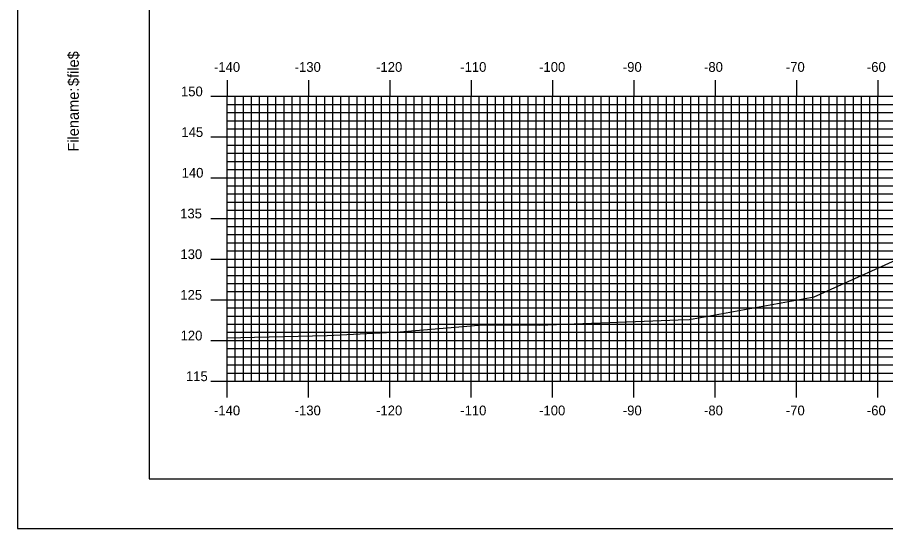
# Model space of a CAD drawing. Extents: x 851753 to 852097, y 364661 to 364881.
# Drawn here: x 851753.5 to 851860.2, y 364661.3 to 364724.1 of the extents above; entities that cross this region are included whole.
import ezdxf

# ---------------------------------------------------------------- set-up
doc = ezdxf.new("R2010")
doc.units = 0
for name, color, linetype in [('BORDER', 7, 'Continuous'), ('H_V ANNOTATION', 7, 'Continuous'), ('MAJOR', 7, 'Continuous'), ('MINOR', 7, 'Continuous'), ('PLOT BOUNDARY', 7, 'Continuous'), ('S_Roadway_Centerline', 7, 'Continuous')]:
    doc.layers.add(name, color=color, linetype=linetype)

msp = doc.modelspace()

# ---------------------------------------------------------------- linework, layer by layer
at = {"layer": 'BORDER'}
msp.add_lwpolyline([(851769.64, 364667.37), (852089.64, 364667.37), (852089.64, 364877.37), (851769.64, 364877.37)], close=True, dxfattribs=at)
at = {"layer": 'MAJOR'}
for p, q in [((851779.24, 364716.37), (851779.24, 364714.37)), ((851789.24, 364716.37), (851789.24, 364714.37)), ((851799.24, 364716.37), (851799.24, 364714.37)), ((851809.24, 364716.37), (851809.24, 364714.37)), ((851819.24, 364716.37), (851819.24, 364714.37)), ((851829.24, 364716.37), (851829.24, 364714.37)), ((851839.24, 364716.37), (851839.24, 364714.37)), ((851849.24, 364716.37), (851849.24, 364714.37)), ((851859.24, 364716.37), (851859.24, 364714.37)), ((851777.24, 364714.37), (851779.24, 364714.37)), ((851779.24, 364714.37), (852059.24, 364714.37)), ((851779.24, 364679.37), (851779.24, 364714.37)), ((851779.24, 364679.37), (851779.24, 364714.37)), ((851779.24, 364714.37), (852059.24, 364714.37)), ((851789.24, 364679.37), (851789.24, 364714.37)), ((851799.24, 364679.37), (851799.24, 364714.37)), ((851809.24, 364679.37), (851809.24, 364714.37)), ((851819.24, 364679.37), (851819.24, 364714.37)), ((851829.24, 364679.37), (851829.24, 364714.37)), ((851839.24, 364679.37), (851839.24, 364714.37)), ((851849.24, 364679.37), (851849.24, 364714.37)), ((851859.24, 364679.37), (851859.24, 364714.37)), ((851777.24, 364709.37), (851779.24, 364709.37)), ((851779.24, 364709.37), (852059.24, 364709.37)), ((851777.24, 364704.37), (851779.24, 364704.37)), ((851779.24, 364704.37), (852059.24, 364704.37)), ((851777.24, 364699.37), (851779.24, 364699.37)), ((851779.24, 364699.37), (852059.24, 364699.37)), ((851777.24, 364694.37), (851779.24, 364694.37)), ((851779.24, 364694.37), (852059.24, 364694.37)), ((851777.24, 364689.37), (851779.24, 364689.37)), ((851779.24, 364689.37), (852059.24, 364689.37)), ((851777.24, 364684.37), (851779.24, 364684.37)), ((851779.24, 364684.37), (852059.24, 364684.37)), ((851777.24, 364679.37), (851779.24, 364679.37)), ((851779.24, 364679.37), (852059.24, 364679.37)), ((851779.24, 364679.37), (852059.24, 364679.37)), ((851779.24, 364677.37), (851779.24, 364679.37)), ((851789.24, 364677.37), (851789.24, 364679.37)), ((851799.24, 364677.37), (851799.24, 364679.37)), ((851809.24, 364677.37), (851809.24, 364679.37)), ((851819.24, 364677.37), (851819.24, 364679.37)), ((851829.24, 364677.37), (851829.24, 364679.37)), ((851839.24, 364677.37), (851839.24, 364679.37)), ((851849.24, 364677.37), (851849.24, 364679.37)), ((851859.24, 364677.37), (851859.24, 364679.37))]:
    msp.add_line(p, q, dxfattribs=at)
at = {"layer": 'MINOR'}
for p, q in [((851780.24, 364679.37), (851780.24, 364714.37)), ((851781.24, 364679.37), (851781.24, 364714.37)), ((851782.24, 364679.37), (851782.24, 364714.37)), ((851783.24, 364679.37), (851783.24, 364714.37)), ((851784.24, 364679.37), (851784.24, 364714.37)), ((851785.24, 364679.37), (851785.24, 364714.37)), ((851786.24, 364679.37), (851786.24, 364714.37)), ((851787.24, 364679.37), (851787.24, 364714.37)), ((851788.24, 364679.37), (851788.24, 364714.37)), ((851790.24, 364679.37), (851790.24, 364714.37)), ((851791.24, 364679.37), (851791.24, 364714.37)), ((851792.24, 364679.37), (851792.24, 364714.37)), ((851793.24, 364679.37), (851793.24, 364714.37)), ((851794.24, 364679.37), (851794.24, 364714.37)), ((851795.24, 364679.37), (851795.24, 364714.37)), ((851796.24, 364679.37), (851796.24, 364714.37)), ((851797.24, 364679.37), (851797.24, 364714.37)), ((851798.24, 364679.37), (851798.24, 364714.37)), ((851800.24, 364679.37), (851800.24, 364714.37)), ((851801.24, 364679.37), (851801.24, 364714.37)), ((851802.24, 364679.37), (851802.24, 364714.37)), ((851803.24, 364679.37), (851803.24, 364714.37)), ((851804.24, 364679.37), (851804.24, 364714.37)), ((851805.24, 364679.37), (851805.24, 364714.37)), ((851806.24, 364679.37), (851806.24, 364714.37)), ((851807.24, 364679.37), (851807.24, 364714.37)), ((851808.24, 364679.37), (851808.24, 364714.37)), ((851810.24, 364679.37), (851810.24, 364714.37)), ((851811.24, 364679.37), (851811.24, 364714.37)), ((851812.24, 364679.37), (851812.24, 364714.37)), ((851813.24, 364679.37), (851813.24, 364714.37)), ((851814.24, 364679.37), (851814.24, 364714.37)), ((851815.24, 364679.37), (851815.24, 364714.37)), ((851816.24, 364679.37), (851816.24, 364714.37)), ((851817.24, 364679.37), (851817.24, 364714.37)), ((851818.24, 364679.37), (851818.24, 364714.37)), ((851820.24, 364679.37), (851820.24, 364714.37)), ((851821.24, 364679.37), (851821.24, 364714.37)), ((851822.24, 364679.37), (851822.24, 364714.37)), ((851823.24, 364679.37), (851823.24, 364714.37)), ((851824.24, 364679.37), (851824.24, 364714.37)), ((851825.24, 364679.37), (851825.24, 364714.37)), ((851826.24, 364679.37), (851826.24, 364714.37)), ((851827.24, 364679.37), (851827.24, 364714.37)), ((851828.24, 364679.37), (851828.24, 364714.37)), ((851830.24, 364679.37), (851830.24, 364714.37)), ((851831.24, 364679.37), (851831.24, 364714.37)), ((851832.24, 364679.37), (851832.24, 364714.37)), ((851833.24, 364679.37), (851833.24, 364714.37)), ((851834.24, 364679.37), (851834.24, 364714.37)), ((851835.24, 364679.37), (851835.24, 364714.37)), ((851836.24, 364679.37), (851836.24, 364714.37)), ((851837.24, 364679.37), (851837.24, 364714.37)), ((851838.24, 364679.37), (851838.24, 364714.37)), ((851840.24, 364679.37), (851840.24, 364714.37)), ((851841.24, 364679.37), (851841.24, 364714.37)), ((851842.24, 364679.37), (851842.24, 364714.37)), ((851843.24, 364679.37), (851843.24, 364714.37)), ((851844.24, 364679.37), (851844.24, 364714.37)), ((851845.24, 364679.37), (851845.24, 364714.37)), ((851846.24, 364679.37), (851846.24, 364714.37)), ((851847.24, 364679.37), (851847.24, 364714.37)), ((851848.24, 364679.37), (851848.24, 364714.37)), ((851850.24, 364679.37), (851850.24, 364714.37)), ((851851.24, 364679.37), (851851.24, 364714.37)), ((851852.24, 364679.37), (851852.24, 364714.37)), ((851853.24, 364679.37), (851853.24, 364714.37)), ((851854.24, 364679.37), (851854.24, 364714.37)), ((851855.24, 364679.37), (851855.24, 364714.37)), ((851856.24, 364679.37), (851856.24, 364714.37)), ((851857.24, 364679.37), (851857.24, 364714.37)), ((851858.24, 364679.37), (851858.24, 364714.37)), ((851779.24, 364713.37), (852059.24, 364713.37)), ((851779.24, 364713.37), (851781.25, 364713.37)), ((851779.24, 364712.37), (852059.24, 364712.37)), ((851779.24, 364712.37), (851781.25, 364712.37)), ((851779.24, 364711.37), (852059.24, 364711.37)), ((851779.24, 364711.37), (851781.25, 364711.37)), ((851779.24, 364710.37), (852059.24, 364710.37)), ((851779.24, 364710.37), (851781.25, 364710.37)), ((851779.24, 364708.37), (852059.24, 364708.37)), ((851779.24, 364708.37), (851781.25, 364708.37)), ((851779.24, 364707.37), (852059.24, 364707.37)), ((851779.24, 364707.37), (851781.25, 364707.37)), ((851779.24, 364706.37), (852059.24, 364706.37)), ((851779.24, 364706.37), (851781.25, 364706.37)), ((851779.24, 364705.37), (852059.24, 364705.37)), ((851779.24, 364705.37), (851781.25, 364705.37)), ((851779.24, 364703.37), (852059.24, 364703.37)), ((851779.24, 364703.37), (851781.25, 364703.37)), ((851779.24, 364702.37), (852059.24, 364702.37)), ((851779.24, 364702.37), (851781.25, 364702.37)), ((851779.24, 364701.37), (852059.24, 364701.37)), ((851779.24, 364701.37), (851781.25, 364701.37)), ((851779.24, 364700.37), (852059.24, 364700.37)), ((851779.24, 364700.37), (851781.25, 364700.37)), ((851779.24, 364698.37), (852059.24, 364698.37)), ((851779.24, 364698.37), (851781.25, 364698.37)), ((851779.24, 364697.37), (852059.24, 364697.37)), ((851779.24, 364697.37), (851781.25, 364697.37)), ((851779.24, 364696.37), (852059.24, 364696.37)), ((851779.24, 364696.37), (851781.25, 364696.37)), ((851779.24, 364695.37), (852059.24, 364695.37)), ((851779.24, 364695.37), (851781.25, 364695.37)), ((851779.24, 364693.37), (852059.24, 364693.37)), ((851779.24, 364693.37), (851781.25, 364693.37)), ((851779.24, 364692.37), (852059.24, 364692.37)), ((851779.24, 364692.37), (851781.25, 364692.37)), ((851779.24, 364691.37), (852059.24, 364691.37)), ((851779.24, 364691.37), (851781.25, 364691.37)), ((851779.24, 364690.37), (852059.24, 364690.37)), ((851779.24, 364690.37), (851781.25, 364690.37)), ((851779.24, 364688.37), (852059.24, 364688.37)), ((851779.24, 364688.37), (851781.25, 364688.37)), ((851779.24, 364687.37), (852059.24, 364687.37)), ((851779.24, 364687.37), (851781.25, 364687.37)), ((851779.24, 364686.37), (852059.24, 364686.37)), ((851779.24, 364686.37), (851781.25, 364686.37)), ((851779.24, 364685.37), (852059.24, 364685.37)), ((851779.24, 364685.37), (851781.25, 364685.37)), ((851779.24, 364683.37), (852059.24, 364683.37)), ((851779.24, 364683.37), (851781.25, 364683.37)), ((851779.24, 364682.37), (852059.24, 364682.37)), ((851779.24, 364682.37), (851781.25, 364682.37)), ((851779.24, 364681.37), (852059.24, 364681.37)), ((851779.24, 364681.37), (851781.25, 364681.37)), ((851779.24, 364680.37), (852059.24, 364680.37)), ((851779.24, 364680.37), (851781.25, 364680.37))]:
    msp.add_line(p, q, dxfattribs=at)
at = {"layer": 'PLOT BOUNDARY'}
msp.add_lwpolyline([(851753.46, 364661.25), (852093.46, 364661.25), (852093.46, 364881.25), (851753.46, 364881.25)], close=True, dxfattribs=at)
at = {"layer": 'S_Roadway_Centerline'}
msp.add_lwpolyline([(851779.24, 364684.71), (851782.62, 364684.78), (851791.54, 364684.99), (851800.46, 364685.43), (851810.63, 364686.3), (851817.6, 364686.24), (851831.58, 364686.78), (851834.69, 364686.89), (851836.07, 364686.94), (851851.43, 364689.74), (851864.3, 364695.56), (851868.15, 364696.54), (851873.42, 364699.29), (851881.21, 364702.76)], dxfattribs=at)

# ---------------------------------------------------------------- texts
at = {"layer": 'BORDER'}
for s, p in [('$file$', (851761.01, 364715.62)), ('Filename:', (851761.01, 364707.57))]:
    msp.add_text(s, height=1.339, rotation=90, dxfattribs=at).set_placement(p)
at = {"layer": 'H_V ANNOTATION'}
for s, p in [('-140', (851777.63, 364717.37)), ('-130', (851787.55, 364717.37)), ('-120', (851797.56, 364717.37)), ('-110', (851807.9, 364717.37)), ('-100', (851817.6, 364717.37)), ('-90', (851827.89, 364717.37)), ('-80', (851837.87, 364717.37)), ('-70', (851847.93, 364717.37)), ('-60', (851857.89, 364717.37)), ('150', (851773.57, 364714.37)), ('145', (851773.62, 364709.37)), ('140', (851773.65, 364704.37)), ('135', (851773.47, 364699.37)), ('130', (851773.5, 364694.37)), ('125', (851773.49, 364689.37)), ('120', (851773.52, 364684.37)), ('115', (851774.18, 364679.37)), ('-140', (851777.63, 364675.17)), ('-130', (851787.55, 364675.17)), ('-120', (851797.56, 364675.17)), ('-110', (851807.9, 364675.17)), ('-100', (851817.6, 364675.17)), ('-90', (851827.89, 364675.17)), ('-80', (851837.87, 364675.17)), ('-70', (851847.93, 364675.17)), ('-60', (851857.89, 364675.17))]:
    msp.add_text(s, height=1.2, dxfattribs=at).set_placement(p)
at = {"layer": 'MAJOR'}
msp.add_text('-', height=0.012, dxfattribs=at).set_placement((851779.23, 364679.37))

doc.saveas('drawing.dxf')
